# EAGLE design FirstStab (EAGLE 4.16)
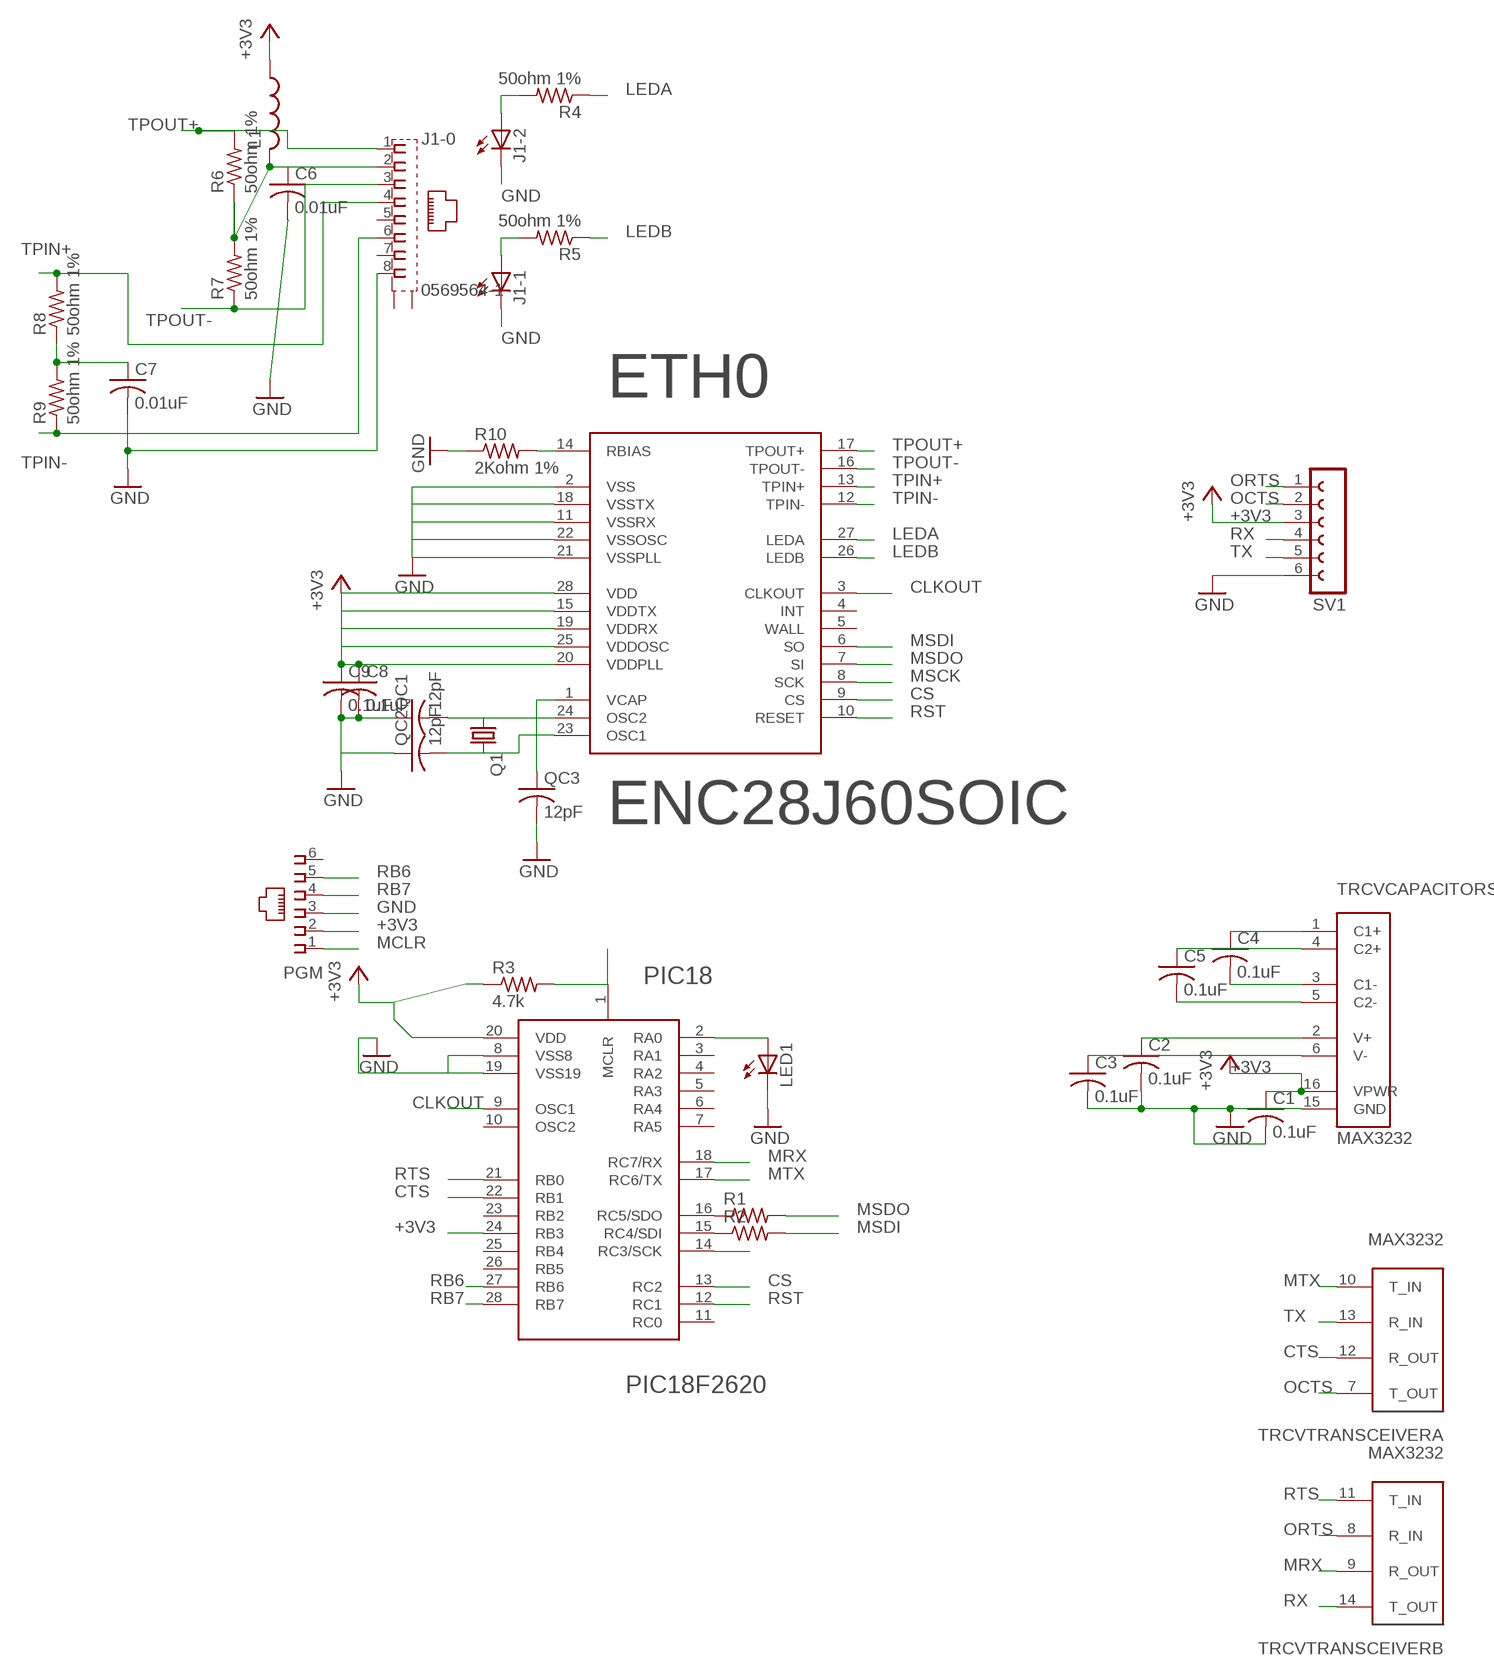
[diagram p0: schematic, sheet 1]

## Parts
C1  0.1uF  C-US025-024X044  [C025-024X044]
C2  0.1uF  C-US025-024X044  [C025-024X044]
C3  0.1uF  C-US025-024X044  [C025-024X044]
C4  0.1uF  C-US025-024X044  [C025-024X044]
C5  0.1uF  C-US025-024X044  [C025-024X044]
C6  0.01uF  C-US050-035X075  [C050-035X075]
C7  0.01uF  C-US050-035X075  [C050-035X075]
C8  0.1uF  C-US025-024X044  [C025-024X044]
C9  0.1uF  C-US025-024X044  [C025-024X044]
ETH0  ENC28J60SOIC  [SO-28W]
J1  0569564-1  [0569564]
L1  L-US0204/5  [0204/5]
LED1  LED3MM  [LED3MM]
PGM  520470-3  [520470-3]
PIC18  PIC18F2620  [SO-28W]
Q1  CRYTALHC49U-H  [HC49U-H]
QC1  12pF  C-US050-024X044  [C050-024X044]
QC2  12pF  C-US050-024X044  [C050-024X044]
QC3  12pF  C-US025-024X044  [C025-024X044]
R1  R-US_0207/7  [0207/7]
R2  R-US_0207/7  [0207/7]
R3  4.7k  R-US_0207/7  [0207/7]
R4  50ohm 1%  R-US_0204/5  [0204/5]
R5  50ohm 1%  R-US_0204/5  [0204/5]
R6  50ohm 1%  R-US_0204/5  [0204/5]
R7  50ohm 1%  R-US_0204/5  [0204/5]
R8  50ohm 1%  R-US_0204/5  [0204/5]
R9  50ohm 1%  R-US_0204/5  [0204/5]
R10  2Kohm 1%  R-US_0204/5  [0204/5]
SV1  FE06-1  [FE06]
TRCV  MAX3232  MAX3232FOO  [SO16]

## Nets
+3V3: C1.1 C8.1 C9.1 ETH0.15(VDDTX) ETH0.19(VDDRX) ETH0.20(VDDPLL) ETH0.25(VDDOSC) ETH0.28(VDD) L1.1 PGM.2 PIC18.20(VDD) PIC18.24(RB3) R3.1 SV1.3 TRCV.16(CAPACITORS:VPWR)
CLKOUT: ETH0.3(CLKOUT) PIC18.9(OSC1)
CS: ETH0.9(CS) PIC18.13(RC2)
CTS: PIC18.22(RB1) TRCV.12(TRANSCEIVERA:R_OUT)
GND: C1.2 C2.2 C3.2 C6.2 C7.2 C8.2 C9.2 ETH0.2(VSS) ETH0.11(VSSRX) ETH0.18(VSSTX) ETH0.21(VSSPLL) ETH0.22(VSSOSC) J1.8 J1.C1(-1:C) J1.C2(-2:C) LED1.K(C) PGM.3 PIC18.8(VSS8) PIC18.19(VSS19) QC1.1 QC2.1 QC3.2 R10.1 SV1.6 TRCV.15(CAPACITORS:GND)
LEDA: ETH0.27(LEDA) R4.1
LEDB: ETH0.26(LEDB) R5.1
MCLR: PGM.1 PIC18.1(MCLR) R3.2
MRX: PIC18.18(RC7/RX) TRCV.9(TRANSCEIVERB:R_OUT)
MSCK: ETH0.8(SCK) PIC18.14(RC3/SCK)
MSDI: ETH0.6(SO) R2.2
MSDO: ETH0.7(SI) R1.2
MTX: PIC18.17(RC6/TX) TRCV.10(TRANSCEIVERA:T_IN)
N$1: ETH0.24(OSC2) Q1.1 QC1.2
N$2: ETH0.23(OSC1) Q1.2 QC2.2
N$3: PIC18.16(RC5/SDO) R1.1
N$4: PIC18.15(RC4/SDI) R2.1
N$5: ETH0.1(VCAP) QC3.1
N$6: C4.1 TRCV.1(CAPACITORS:C1+)
N$7: C5.1 TRCV.4(CAPACITORS:C2+)
N$8: C4.2 TRCV.3(CAPACITORS:C1-)
N$9: C5.2 TRCV.5(CAPACITORS:C2-)
N$10: C2.1 TRCV.2(CAPACITORS:V+)
N$11: C3.1 TRCV.6(CAPACITORS:V-)
N$14: C6.1 J1.2 L1.2 R6.1 R7.2
N$15: C7.1 R8.1 R9.2
N$16: J1.A2(-2:A) R4.2
N$17: J1.A1(-1:A) R5.2
N$19: ETH0.14(RBIAS) R10.2
N$25: LED1.A PIC18.2(RA0)
OCTS: SV1.2 TRCV.7(TRANSCEIVERA:T_OUT)
ORTS: SV1.1 TRCV.8(TRANSCEIVERB:R_IN)
RB6: PGM.5 PIC18.27(RB6)
RB7: PGM.4 PIC18.28(RB7)
RST: ETH0.10(RESET) PIC18.12(RC1)
RTS: PIC18.21(RB0) TRCV.11(TRANSCEIVERB:T_IN)
RX: SV1.4 TRCV.14(TRANSCEIVERB:T_OUT)
TPIN+: ETH0.13(TPIN+) J1.4 R8.2
TPIN-: ETH0.12(TPIN-) J1.6 R9.1
TPOUT+: ETH0.17(TPOUT+) J1.1 R6.2
TPOUT-: ETH0.16(TPOUT-) J1.3 R7.1
TX: SV1.5 TRCV.13(TRANSCEIVERA:R_IN)
Unconnected: ETH0.4(INT) ETH0.5(WALL) J1.5 J1.7 J1.S1(-0:S1) J1.S2(-0:S2) PGM.6 PIC18.3(RA1) PIC18.4(RA2) PIC18.5(RA3) PIC18.6(RA4) PIC18.7(RA5) PIC18.10(OSC2) PIC18.11(RC0) PIC18.23(RB2) PIC18.25(RB4) PIC18.26(RB5)

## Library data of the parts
C1-C9 QC1-QC3 = rcl:C-US: CAPACITOR, American symbol
ETH0 = serial_ethernet_parts:ENC28J60
J1 = con-amp:0569564-*: MODULAR JACK 8 POS., RIGHT ANGLE, LOW PROFILE WITH LEDS Source: http://ecommas.tycoelectronics.com/.. 569564_K.pdf
L1 = rcl:L-US: INDUCTOR, American symbol
LED1 = led:LED: LED
PGM = con-amp:520470-3: AMP connector
PIC18 = serial_ethernet_parts:PIC18F2620
Q1 = crystal:CRYTAL: CRYSTAL
R1-R10 = rcl:R-US_: RESISTOR, American symbol
SV1 = con-lsta:FE06-1: FEMALE HEADER
TRCV = serial_ethernet_parts:MAX3232

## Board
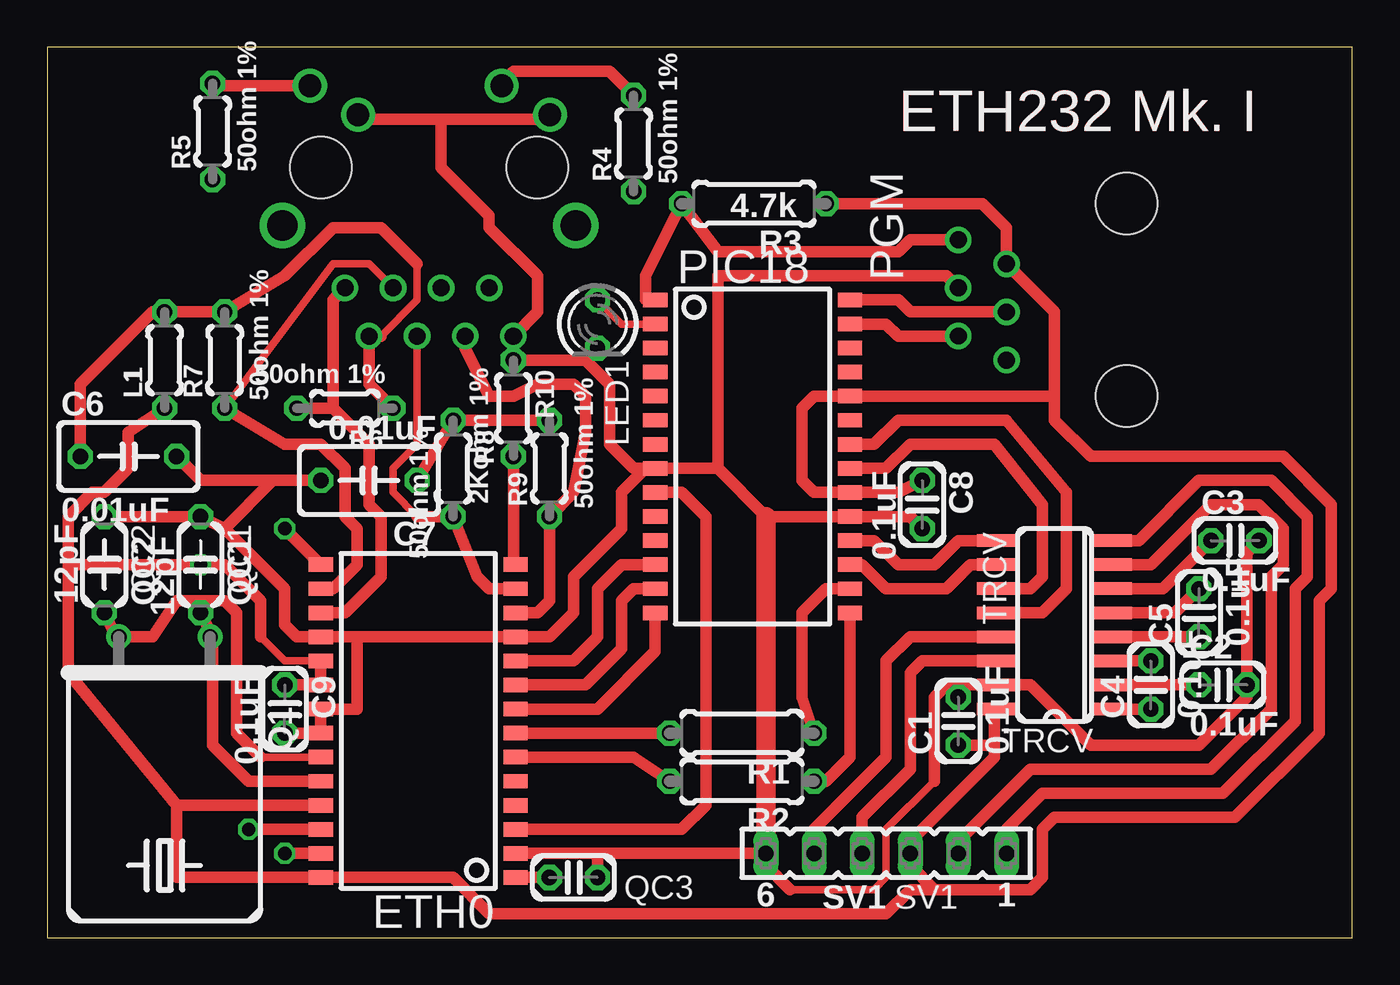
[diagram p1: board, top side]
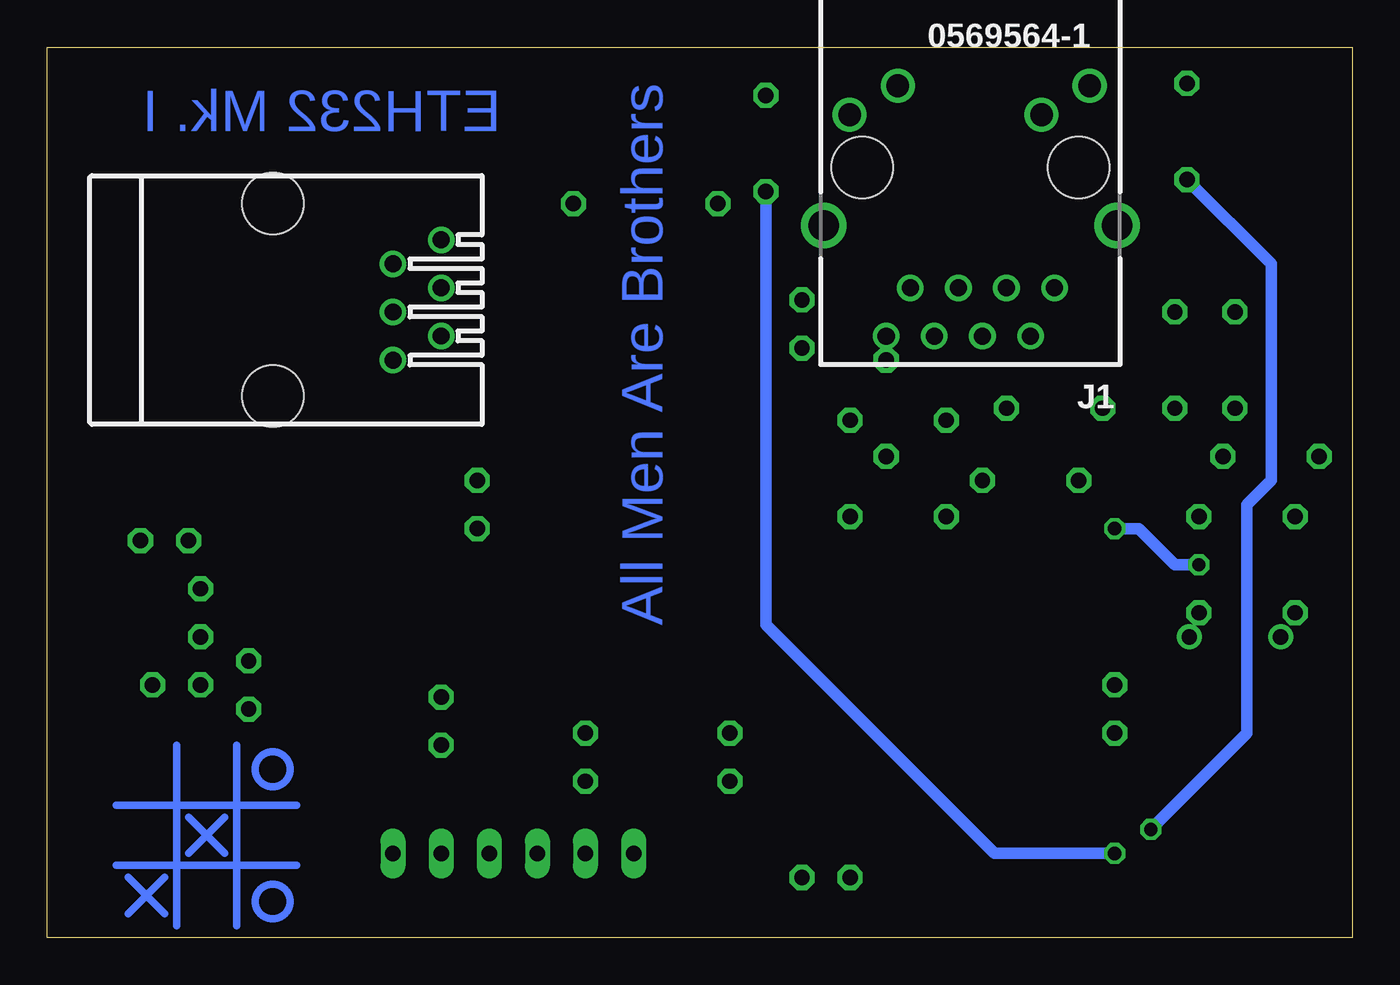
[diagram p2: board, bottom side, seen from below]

Size 68.89 x 46.98 mm. Coordinates in mm from the lower left corner, seen from the top.
Outline: 0,0 68.89,0 68.89,46.98 0,46.98 0,0
Copper layers (1*16): Top 0.035mm / dielectric 1.5mm / Bottom 0.035mm
Design rules "10mils": minimum track width 10mil, minimum drill 24mil, track to track 10mil, track to pad 10mil, pad to pad 10mil, via to via 10mil, smd to smd 10mil, copper to edge 40mil, drill to drill 10mil, minimum pad ring 10mil, minimum via ring 8mil, stop-mask expansion 0mil, vias tented up to drill 0mil, thermal gap 10mil

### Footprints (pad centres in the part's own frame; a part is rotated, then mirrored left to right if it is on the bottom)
C025-024X044 = drill 0.813 octagon: 1 -1.27,0; 2 1.27,0
C050-035X075 = drill 0.813 octagon: 1 -2.54,0; 2 2.54,0
SO-28W = smd 0.762 x 1.27: 1 -7.62,-5.207; 2 -6.35,-5.207; 3 -5.08,-5.207; 4 -3.81,-5.207; 5 -2.54,-5.207; 6 -1.27,-5.207; 7 0,-5.207; 8 1.27,-5.207; 9 2.54,-5.207; 10 3.81,-5.207; 11 5.08,-5.207; 12 6.35,-5.207; 13 7.62,-5.207; 14 8.89,-5.207; 15 8.89,5.08; 16 7.62,5.08; 17 6.35,5.08; 18 5.08,5.08; 19 3.81,5.08; 20 2.54,5.08; 21 1.27,5.08; 22 0,5.08; 23 -1.27,5.08; 24 -2.54,5.08; 25 -3.81,5.08; 26 -5.08,5.08; 27 -6.35,5.08; 28 -7.62,5.08
0569564 = drill 0.9 round: 1 -4.445,6.35; 2 -3.175,8.89; 3 -1.905,6.35; 4 -0.635,8.89; 5 0.635,6.35; 6 1.905,8.89; 7 3.175,6.35; 8 4.445,8.89 | drill 1.2 round: A1 -6.295,-4.32; A2 3.835,-4.32; C1 -3.755,-2.79; C2 6.375,-2.79 | drill 1.6 round: S1 -7.745,3.05; S2 7.745,3.05 | hole 3.25: -5.715,0; 5.715,0
0204/5 = drill 0.813 octagon: 1 -2.54,0; 2 2.54,0
LED3MM = drill 0.813 octagon: A -1.27,0; K 1.27,0
520470-3 = drill 0.889 round: 1 -3.175,8.89; 2 -1.905,6.35; 3 -0.635,8.89; 4 0.635,6.35; 5 1.905,8.89; 6 3.175,6.35 | hole 3.251: -5.08,0; 5.08,0
HC49U-H = drill 0.813 round: 1 -2.413,-5.08; 2 2.413,-5.08
C050-024X044 = drill 0.813 octagon: 1 -2.54,0; 2 2.54,0
0207/7 = drill 0.813 octagon: 1 -3.81,0; 2 3.81,0
FE06 = drill 0.813 long: 1 -6.35,0; 2 -3.81,0; 3 -1.27,0; 4 1.27,0; 5 3.81,0; 6 6.35,0
SO16 = smd 0.66 x 2.032: 1 -4.445,-3.073; 2 -3.175,-3.073; 3 -1.905,-3.073; 4 -0.635,-3.073; 5 0.635,-3.073; 6 1.905,-3.073; 7 3.175,-3.073; 8 4.445,-3.073; 9 4.445,3.073; 10 3.175,3.073; 11 1.905,3.073; 12 0.635,3.073; 13 -0.635,3.073; 14 -1.905,3.073; 15 -3.175,3.073; 16 -4.445,3.073

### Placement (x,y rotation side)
C1  48.09,11.43 90 top
C2  62.07,13.33 0 top
C3  62.7,20.95 0 top
C4  58.26,13.33 90 top
C5  60.8,17.14 90 top
C6  4.28,25.39 0 top
C7  16.98,24.12 180 top
C8  46.19,22.86 270 top
C9  12.54,12.06 270 top
ETH0  19.52,10.79 90 top
J1  20.16,40.64 180 bottom
L1  6.19,30.47 90 top
LED1  29.04,32.38 270 top
PGM  56.98,33.65 270 bottom
PIC18  37.3,26.03 270 top
Q1  6.19,10.79 180 top
QC1  8.09,19.68 270 top
QC2  3.01,19.68 270 top
QC3  27.77,3.17 0 top
R1  36.66,10.79 180 top
R2  36.66,8.25 180 top
R3  37.3,38.73 180 top
R4  30.95,41.91 90 top
R5  8.72,42.54 90 top
R6  15.71,27.93 180 top
R7  9.36,30.47 90 top
R8  21.43,24.76 270 top
R9  26.5,24.76 90 top
R10  24.6,27.93 270 top
SV1  44.28,4.44 180 top
TRCV  53.17,16.5 90 top

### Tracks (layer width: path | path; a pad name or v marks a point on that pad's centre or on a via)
+3V3  (via drill 0.7)
  Top 0.406: ETH0.19 12.54,14.6 11.27,15.87
  Top 0.61: 53.17,28.57 53.17,27.3 55.08,25.39 65.24,25.39 67.78,22.86 67.78,18.41 67.15,17.77 67.15,10.79 62.7,6.35 53.17,6.35 52.54,5.71 52.54,3.17 51.91,2.54 46.83,2.54 | 53.17,28.57 53.17,33.02 PGM.2 50.63,37.46 49.37,38.73 R3.1 | ETH0.19 ETH0.20 C9.1 | 6.82,6.98 ETH0.25 | 6.82,6.98 6.82,3.17 ETH0.28 21.43,3.17 23.33,1.26 44.28,1.26 45.55,2.54 46.83,2.54 | L1.1 4.28,26.66 4.28,24.76 3.01,23.49 2.38,23.49 1.1,22.22 1.1,19.68 | 1.1,19.68 1.1,13.96 6.82,6.98 | 11.27,15.87 11.27,17.77 9.36,19.68 v8.09,19.68 1.1,19.68 | 50,12.06 TRCV.16 | 46.83,2.54 45.55,3.8 SV1.3 45.55,5.08 50,9.52 50,10.15 | 50,12.06 50.1,11.96 | 50,10.15 50,12.06 | 53.17,28.57 PIC18.24 40.48,28.57 39.84,27.93 39.84,24.12 40.48,23.49 PIC18.20 44.92,23.49 C8.1 | 50,10.15 C1.1 | v12.54,21.59 ETH0.15
  Bottom 0.61: v8.09,19.68 9.36,19.68 11.27,21.59 v12.54,21.59
CLKOUT
  Top 0.61: PIC18.9 33.49,23.49 34.76,22.22 34.76,6.98 33.49,5.71 ETH0.3 25.87,5.71
CS
  Top 0.61: PIC18.13 30.95,18.41 30.31,17.77 30.31,15.23 28.41,13.33 ETH0.9
CTS
  Top 0.61: PIC18.22 43.65,26.03 44.92,27.3 50.63,27.3 53.81,23.49 53.81,18.41 52.54,17.14 TRCV.12 50,17.14
GND
  Top 0.406: 46.83,8.25 44.28,5.71 44.28,3.17 43.65,2.54 39.2,2.54 | 28.41,30.47 LED1.K
  Top 0.61: QC2.1 QC1.1 9.36,21.59 | 16.34,15.87 ETH0.18 13.17,15.87 12.54,16.5 12.54,18.41 9.36,21.59 | 16.34,15.87 ETH0.11 26.5,15.87 27.77,17.14 27.77,19.04 30.31,21.59 30.31,23.49 31.59,24.76 | 16.34,15.87 16.34,12.06 ETH0.21 ETH0.22 C9.2 | 31.59,24.76 PIC18.8 35.4,24.76 | 35.4,24.76 37.94,22.22 PIC18.19 45.55,22.22 C8.2 | PGM.3 47.46,34.92 35.4,34.92 35.4,24.76 | C3.2 63.34,20.32 C2.2 63.34,12.7 60.8,10.15 55.08,10.15 51.91,13.33 TRCV.15 48.09,13.33 | 39.2,2.54 37.94,3.8 SV1.6 29.04,4.44 | 48.09,13.33 47.46,13.33 46.83,12.7 46.83,8.25 | 11.9,24.12 C7.2 | 11.9,24.12 8.09,24.12 C6.2 | 31.59,24.76 35.4,24.76 | 31.59,24.76 30.95,24.76 29.68,26.03 29.68,29.2 28.41,30.47 R10.1 J1.8 25.87,33.02 25.87,34.92 23.33,37.46 23.33,38.1 20.79,40.64 20.79,43.18 | J1.C1 16.4,43.23 16.34,43.18 20.79,43.18 | J1.C2 26.53,43.2 26.5,43.18 20.79,43.18 | 9.36,21.59 11.9,24.12 | 48.09,13.33 C1.2 | 24.6,4.44 ETH0.2 29.04,4.44 | 29.04,4.44 QC3.2
  Top 1.016: 37.94,22.22 SV1.6
LEDA  (via drill 0.7)
  Top 0.61: v12.54,4.44 ETH0.27
  Bottom 0.61: R4.1 30.95,16.5 18.88,4.44 v12.54,4.44
LEDB  (via drill 0.7)
  Top 0.61: v10.63,5.71 ETH0.26
  Bottom 0.61: v10.63,5.71 5.55,10.79 5.55,22.86 4.28,24.12 4.28,35.56 R5.1
MCLR
  Top 0.61: PIC18.1 31.59,33.65 31.59,34.92 R3.2 35.4,36.19 44.92,36.19 45.55,36.83 PGM.1
MRX
  Top 0.61: PIC18.18 43.65,20.95 44.92,19.68 46.83,19.68 48.09,20.95 TRCV.9
MSCK
  Top 0.61: PIC18.14 32.09,15.11 29.04,12.06 ETH0.8 25.87,12.06
MSDI
  Top 0.61: 25.87,9.52 ETH0.6 30.95,9.52 R2.2
MSDO
  Top 0.61: 25.87,10.79 ETH0.7 R1.2
MTX
  Top 0.61: PIC18.17 43.02,19.68 44.28,18.41 47.46,18.41 48.73,19.68 TRCV.10
N$1
  Top 0.61: ETH0.24 10.63,8.25 8.72,10.15 8.72,15.87 | 8.72,15.87 QC1.2 | 8.72,15.87 Q1.1
N$2
  Top 0.406: 11.27,9.52 ETH0.23
  Top 0.61: QC2.2 3.65,15.87 Q1.2 5.55,15.87 6.82,17.77 9.36,17.77 9.99,17.14 9.99,10.79 11.27,9.52
N$3
  Top 0.61: R1.1 39.84,12.7 39.84,17.14 41.11,18.41 PIC18.16
N$4
  Top 0.61: R2.1 41.11,8.25 42.38,9.52 PIC18.15
N$5
  Top 0.61: 24.6,3.17 ETH0.1 QC3.1
N$6
  Top 0.61: TRCV.1 C4.1
N$7
  Top 0.61: TRCV.4 C5.1
N$8
  Top 0.61: TRCV.3 C4.2
N$9
  Top 0.61: TRCV.5 59.52,17.14 C5.2
N$10
  Top 0.61: TRCV.2 C2.1
N$11
  Top 0.61: TRCV.6 58.89,18.41 C3.1
N$12
  Bottom 0.406: 58.89,10.15 58.89,0.63
N$13
  Bottom 0.406: 62.07,0.63 62.07,10.15
N$14
  Top 0.406: 17.61,31.75 19.52,33.65 19.52,35.56
  Top 0.61: 17.61,31.75 J1.2 16.98,29.2 R6.1 | 19.52,35.56 17.61,37.46 15.07,37.46 12.54,34.92 R7.2 L1.2 5.55,33.02 1.74,29.2 C6.1
N$15
  Top 0.61: R9.2 R8.1 C7.1
N$16
  Top 0.61: J1.A2 23.99,45.11 24.6,45.72 29.68,45.72 R4.2
N$17
  Top 0.61: J1.A1 8.85,44.96 R5.2
N$18
  Bottom 0.406: 65.24,6.98 55.71,6.98
N$19
  Top 0.61: ETH0.14 24.6,19.68 R10.2
N$20
  Bottom 0.406: 55.71,3.8 65.24,3.8
N$21
  Bottom 0.406: 59.52,6.35 61.43,4.44
N$22
  Bottom 0.406: 61.43,6.35 59.52,4.44
N$23
  Bottom 0.406: 62.7,3.17 64.61,1.26
N$24
  Bottom 0.406: 64.61,3.17 62.7,1.26
N$25
  Top 0.406: PIC18.2 30.31,32.38 LED1.A
OCTS
  Top 0.61: TRCV.7 58.26,19.68 61.43,22.86 63.97,22.86 65.24,21.59 65.24,19.68 64.61,19.04 64.61,12.06 61.43,8.88 51.91,8.88 48.09,5.08 SV1.2
ORTS
  Top 0.61: TRCV.8 57.62,20.95 60.8,24.12 64.61,24.12 66.51,22.22 66.51,19.04 65.88,18.41 65.88,11.43 62.07,7.62 52.54,7.62 50.63,5.71 SV1.1
RB6
  Top 0.61: PIC18.27 44.28,32.38 44.92,31.75 PGM.5
RB7
  Top 0.61: PIC18.28 44.92,33.65 45.55,33.02 PGM.4
RST
  Top 0.61: 32.22,19.68 PIC18.12 30.31,19.68 29.04,18.41 29.04,15.87 27.77,14.6 ETH0.10
RTS
  Top 0.61: PIC18.21 44.28,24.76 45.55,26.03 50,26.03 52.54,22.86 52.54,19.04 51.91,18.41 TRCV.11 50,18.41
RX
  Top 0.61: SV1.4 43.02,6.35 45.55,8.88 45.55,13.96 46.19,14.6 TRCV.14
TPIN+
  Top 0.406: 19.52,22.22 18.25,23.49 18.25,24.76 19.52,26.03 J1.4
  Top 0.61: ETH0.13 23.33,18.41 22.7,19.04 R8.2 19.52,22.22
TPIN-
  Top 0.61: 24.6,17.14 ETH0.12 25.87,17.14 26.5,17.77 R9.1 27.77,23.49 28.41,26.66 28.41,28.57 27.77,29.2 25.87,29.2 24.6,28.57 23.33,28.57 22.06,31.11 J1.6
TPOUT+
  Top 0.61: ETH0.17 15.71,17.14 17.61,19.04 17.61,22.22 16.98,22.86 16.98,26.03 15.07,27.93 | J1.1 15.07,33.65 15.07,27.93 | 15.07,27.93 R6.2
TPOUT-
  Top 0.406: J1.3 16.98,35.56 15.07,35.56 R7.1
  Top 0.61: ETH0.16 15.07,18.41 16.34,19.68 16.34,21.59 15.71,22.22 15.71,24.76 14.44,26.03 12.54,26.03 R7.1
TX
  Top 0.61: SV1.5 40.48,5.71 44.28,9.52 44.28,14.6 45.55,15.87 TRCV.13
(copper drawn outside any net)
  shapes: Bottom circle x2

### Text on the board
Top: ETH232 Mk. I
Bottom: All Men Are Brothers | ETH232 Mk. I
tPlace: ETH232 Mk. I
tNames: R5 | 50ohm 1% | R4 | 50ohm 1% | 4.7k | R3 | 50ohm 1% | 2Kohm 1% | R10 | L1 | R7 | 50ohm 1% | C6 | R6 | 50ohm 1% | 0.01uF | R8 | 0.1uF | C8 | R9 | 50ohm 1% | 12pF | 0.01uF | C7 | C3 | QC2 | 12pF | QC1 | 0.1uF | C5 | C2 | 0.1uF | 0.1uF | C9 | Q1 | C4 | 0.1uF | 0.1uF | C1 | 0.1uF | R1 | R2 | 6 | SV1 | 1
bNames: 0569564-1 | J1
